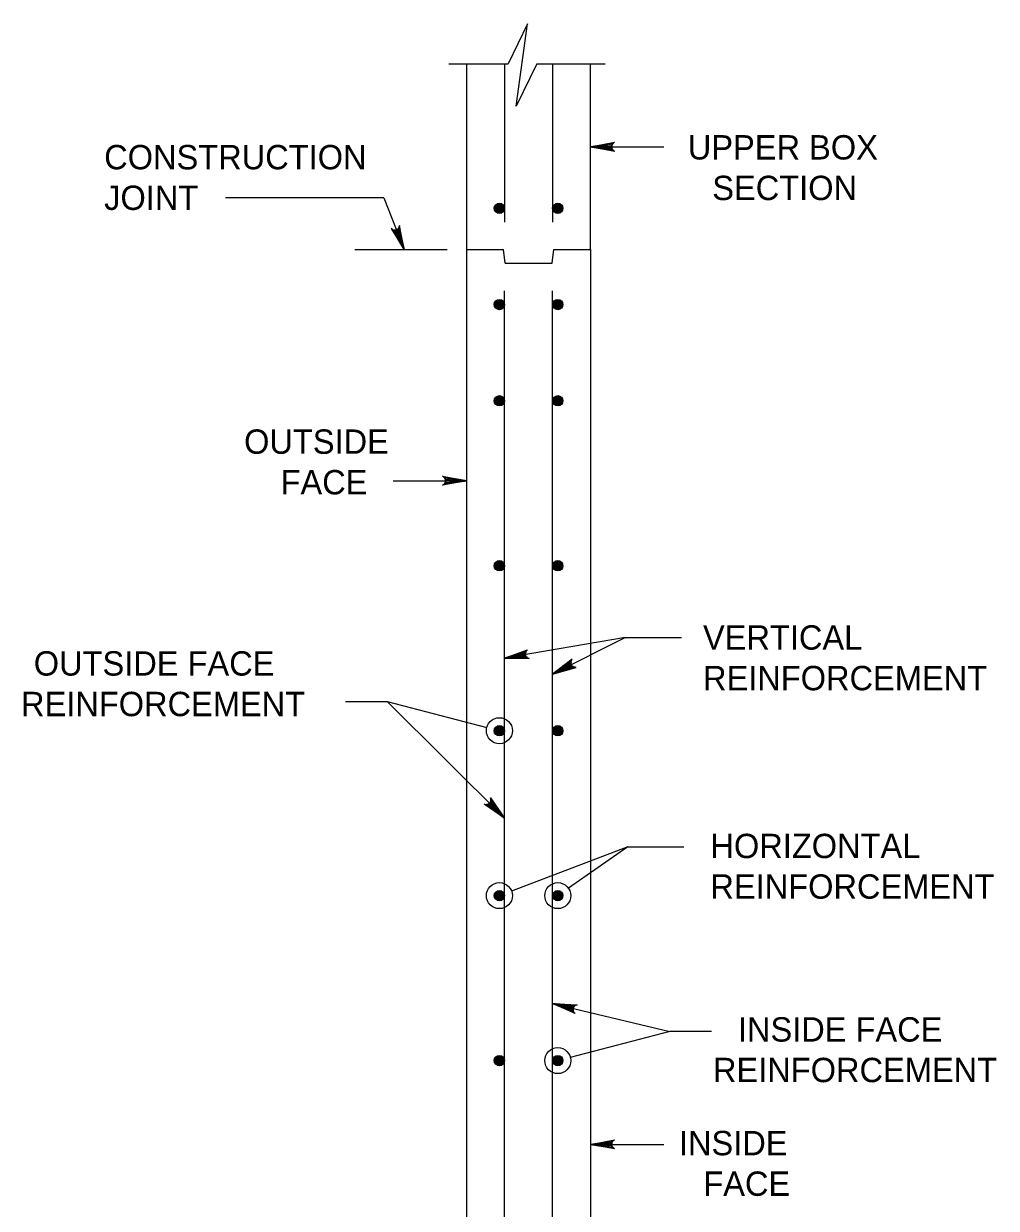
# Model space of a CAD drawing. Extents: x -6420 to 49575, y -4552 to 11624.
# Drawn here: x 2887 to 3280, y 6358.6 to 6837.4 of the extents above; entities that cross this region are included whole.
import ezdxf

# ---------------------------------------------------------------- set-up
doc = ezdxf.new("R2010")
doc.units = 0
doc.layers.add('1', color=7, linetype='Continuous')

msp = doc.modelspace()

# ---------------------------------------------------------------- linework, layer by layer
at = {"layer": '1'}
for p, q in [((3058.81, 6821.09), (3082.78, 6821.09)), ((3065.99, 6746.09), (3065.99, 6821.09)), ((3081.28, 6821.09), (3081.28, 6757.21)), ((3094.33, 6821.09), (3121.91, 6821.09)), ((3100.69, 6821.09), (3100.69, 6757.21)), ((3115.99, 6746.09), (3115.99, 6821.09)), ((3115.99, 6787.61), (3145.68, 6787.61)), ((3032.51, 6767.06), (2968.54, 6767.06)), ((3032.51, 6767.06), (3040.7, 6746.09)), ((3020.79, 6746.09), (3058.12, 6746.09)), ((3065.99, 6146.09), (3065.99, 6746.09)), ((3065.99, 6746.09), (3080.81, 6746.09)), ((3081.5, 6740.54), (3080.81, 6746.09)), ((3100.48, 6740.54), (3101.18, 6746.09)), ((3101.18, 6746.09), (3115.99, 6746.09)), ((3115.99, 6746.09), (3115.99, 6201.65)), ((3081.5, 6740.54), (3100.48, 6740.54)), ((3081.28, 6175.26), (3081.28, 6729.43)), ((3100.69, 6168.31), (3100.69, 6729.43)), ((3036.3, 6652.67), (3065.99, 6652.67)), ((3130.14, 6589.33), (3081.28, 6580.92)), ((3130.14, 6589.33), (3100.69, 6574.45)), ((3130.14, 6589.33), (3152.78, 6589.33)), ((3017.02, 6563.46), (3033.9, 6563.46)), ((3081.28, 6516.35), (3033.9, 6563.46)), ((3033.9, 6563.46), (3074.12, 6552.98)), ((3079.2, 6551.65), (3079.2, 6551.65)), ((3131.15, 6504.68), (3084.11, 6486.85)), ((3131.15, 6504.68), (3107.09, 6487.98)), ((3131.15, 6504.68), (3153.8, 6504.68)), ((3079.2, 6484.99), (3079.2, 6484.99)), ((3102.78, 6484.99), (3102.78, 6484.99)), ((3100.69, 6441.41), (3148.08, 6430.13)), ((3148.08, 6430.13), (3107.86, 6419.64)), ((3164.96, 6430.13), (3148.08, 6430.13)), ((3102.78, 6418.32), (3102.78, 6418.32)), ((3115.99, 6384.48), (3145.68, 6384.48))]:
    msp.add_line(p, q, dxfattribs=at)
for points in [[(3094.33, 6821.09), (3086, 6804.08), (3090.53, 6837.38), (3082.78, 6821.09)], [(3115.99, 6787.61), (3125.77, 6789.45), (3125.4, 6789.19), (3125.02, 6788.93), (3124.83, 6788.6), (3124.63, 6788.27), (3124.58, 6787.94), (3124.52, 6787.61), (3124.58, 6787.29), (3124.63, 6786.96), (3124.83, 6786.63), (3125.02, 6786.3), (3125.4, 6786.04), (3125.77, 6785.78), (3115.99, 6787.61), (3125.4, 6786.04), (3125.02, 6786.3), (3115.99, 6787.61), (3124.83, 6786.63), (3124.63, 6786.96), (3115.99, 6787.61), (3124.58, 6787.29), (3124.52, 6787.61), (3115.99, 6787.61), (3124.58, 6787.94), (3124.63, 6788.27), (3115.99, 6787.61), (3124.83, 6788.6), (3125.02, 6788.93), (3115.99, 6787.61), (3125.4, 6789.19)], [(3040.7, 6746.09), (3038.85, 6755.88), (3038.74, 6755.43), (3038.64, 6754.98), (3038.4, 6754.68), (3038.17, 6754.38), (3037.88, 6754.21), (3037.6, 6754.04), (3037.27, 6753.97), (3036.94, 6753.9), (3036.57, 6753.97), (3036.19, 6754.03), (3035.81, 6754.28), (3035.43, 6754.54), (3040.7, 6746.09), (3035.81, 6754.28), (3036.19, 6754.03), (3040.7, 6746.09), (3036.57, 6753.97), (3036.94, 6753.9), (3040.7, 6746.09), (3037.27, 6753.97), (3037.6, 6754.04), (3040.7, 6746.09), (3037.88, 6754.21), (3038.17, 6754.38), (3040.7, 6746.09), (3038.4, 6754.68), (3038.64, 6754.98), (3040.7, 6746.09), (3038.74, 6755.43)], [(3065.99, 6652.67), (3056.2, 6650.83), (3056.58, 6651.1), (3056.96, 6651.36), (3057.15, 6651.69), (3057.35, 6652.01), (3057.4, 6652.34), (3057.46, 6652.67), (3057.4, 6653), (3057.35, 6653.33), (3057.15, 6653.65), (3056.96, 6653.98), (3056.58, 6654.24), (3056.2, 6654.5), (3065.99, 6652.67), (3056.58, 6654.24), (3056.96, 6653.98), (3065.99, 6652.67), (3057.15, 6653.65), (3057.35, 6653.33), (3065.99, 6652.67), (3057.4, 6653), (3057.46, 6652.67), (3065.99, 6652.67), (3057.4, 6652.34), (3057.35, 6652.01), (3065.99, 6652.67), (3057.15, 6651.69), (3056.96, 6651.36), (3065.99, 6652.67), (3056.58, 6651.1)], [(3081.28, 6580.92), (3090.62, 6584.39), (3090.29, 6584.07), (3089.96, 6583.75), (3089.83, 6583.39), (3089.69, 6583.03), (3089.69, 6582.7), (3089.69, 6582.37), (3089.8, 6582.05), (3089.91, 6581.74), (3090.16, 6581.45), (3090.41, 6581.16), (3090.82, 6580.97), (3091.24, 6580.77), (3081.28, 6580.92), (3090.82, 6580.97), (3090.41, 6581.16), (3081.28, 6580.92), (3090.16, 6581.45), (3089.91, 6581.74), (3081.28, 6580.92), (3089.8, 6582.05), (3089.69, 6582.37), (3081.28, 6580.92), (3089.69, 6582.7), (3089.69, 6583.03), (3081.28, 6580.92), (3089.83, 6583.39), (3089.96, 6583.75), (3081.28, 6580.92), (3090.29, 6584.07)], [(3100.69, 6574.45), (3110.25, 6577.22), (3109.8, 6577.29), (3109.35, 6577.35), (3109.02, 6577.56), (3108.7, 6577.76), (3108.5, 6578.03), (3108.31, 6578.3), (3108.21, 6578.61), (3108.11, 6578.93), (3108.14, 6579.31), (3108.16, 6579.69), (3108.38, 6580.1), (3108.6, 6580.5), (3100.69, 6574.45), (3108.38, 6580.1), (3108.16, 6579.69), (3100.69, 6574.45), (3108.14, 6579.31), (3108.11, 6578.93), (3100.69, 6574.45), (3108.21, 6578.61), (3108.31, 6578.3), (3100.69, 6574.45), (3108.5, 6578.03), (3108.7, 6577.76), (3100.69, 6574.45), (3109.02, 6577.56), (3109.35, 6577.35), (3100.69, 6574.45), (3109.8, 6577.29)], [(3081.28, 6516.35), (3073.05, 6521.95), (3073.5, 6521.87), (3073.95, 6521.79), (3074.32, 6521.88), (3074.69, 6521.98), (3074.96, 6522.17), (3075.23, 6522.36), (3075.43, 6522.64), (3075.62, 6522.91), (3075.71, 6523.28), (3075.8, 6523.65), (3075.72, 6524.1), (3075.64, 6524.55), (3081.28, 6516.35), (3075.72, 6524.1), (3075.8, 6523.65), (3081.28, 6516.35), (3075.71, 6523.28), (3075.62, 6522.91), (3081.28, 6516.35), (3075.43, 6522.64), (3075.23, 6522.36), (3081.28, 6516.35), (3074.96, 6522.17), (3074.69, 6521.98), (3081.28, 6516.35), (3074.32, 6521.88), (3073.95, 6521.79), (3081.28, 6516.35), (3073.5, 6521.87)], [(3100.69, 6441.41), (3110.64, 6440.93), (3110.21, 6440.76), (3109.78, 6440.59), (3109.52, 6440.32), (3109.25, 6440.05), (3109.12, 6439.74), (3108.99, 6439.43), (3108.97, 6439.1), (3108.95, 6438.77), (3109.06, 6438.41), (3109.17, 6438.04), (3109.48, 6437.7), (3109.79, 6437.36), (3100.69, 6441.41), (3109.48, 6437.7), (3109.17, 6438.04), (3100.69, 6441.41), (3109.06, 6438.41), (3108.95, 6438.77), (3100.69, 6441.41), (3108.97, 6439.1), (3108.99, 6439.43), (3100.69, 6441.41), (3109.12, 6439.74), (3109.25, 6440.05), (3100.69, 6441.41), (3109.52, 6440.32), (3109.78, 6440.59), (3100.69, 6441.41), (3110.21, 6440.76)], [(3115.99, 6384.48), (3125.77, 6386.31), (3125.4, 6386.05), (3125.02, 6385.79), (3124.83, 6385.46), (3124.63, 6385.13), (3124.58, 6384.8), (3124.52, 6384.48), (3124.58, 6384.15), (3124.63, 6383.82), (3124.83, 6383.49), (3125.02, 6383.16), (3125.4, 6382.9), (3125.77, 6382.64), (3115.99, 6384.48), (3125.4, 6382.9), (3125.02, 6383.16), (3115.99, 6384.48), (3124.83, 6383.49), (3124.63, 6383.82), (3115.99, 6384.48), (3124.58, 6384.15), (3124.52, 6384.48), (3115.99, 6384.48), (3124.58, 6384.8), (3124.63, 6385.13), (3115.99, 6384.48), (3124.83, 6385.46), (3125.02, 6385.79), (3115.99, 6384.48), (3125.4, 6386.05)]]:
    msp.add_lwpolyline(points, dxfattribs=at)
for centre, radius in [((3079.2, 6762.76), 2.08), ((3079.2, 6762.76), 1.94), ((3102.78, 6762.76), 2.08), ((3102.78, 6762.76), 1.94), ((3079.2, 6762.76), 1.79), ((3079.2, 6762.76), 1.64), ((3079.2, 6762.76), 1.49), ((3079.2, 6762.76), 1.34), ((3079.2, 6762.76), 1.2), ((3079.2, 6762.76), 1.05), ((3079.2, 6762.76), 0.9), ((3079.2, 6762.76), 0.752), ((3079.2, 6762.76), 0.604), ((3079.2, 6762.76), 0.456), ((3079.2, 6762.76), 0.308), ((3079.2, 6762.76), 0.16), ((3102.78, 6762.76), 1.79), ((3102.78, 6762.76), 1.64), ((3102.78, 6762.76), 1.49), ((3102.78, 6762.76), 1.34), ((3102.78, 6762.76), 1.2), ((3102.78, 6762.76), 1.05), ((3102.78, 6762.76), 0.9), ((3102.78, 6762.76), 0.752), ((3102.78, 6762.76), 0.604), ((3102.78, 6762.76), 0.456), ((3102.78, 6762.76), 0.308), ((3102.78, 6762.76), 0.16), ((3079.2, 6723.87), 2.08), ((3079.2, 6723.87), 1.94), ((3079.2, 6723.87), 1.79), ((3079.2, 6723.87), 1.64), ((3079.2, 6723.87), 1.49), ((3079.2, 6723.87), 1.34), ((3079.2, 6723.87), 1.2), ((3079.2, 6723.87), 1.05), ((3079.2, 6723.87), 0.9), ((3079.2, 6723.87), 0.752), ((3079.2, 6723.87), 0.604), ((3079.2, 6723.87), 0.456), ((3079.2, 6723.87), 0.308), ((3079.2, 6723.87), 0.16), ((3102.78, 6723.87), 2.08), ((3102.78, 6723.87), 1.94), ((3102.78, 6723.87), 1.79), ((3102.78, 6723.87), 1.64), ((3102.78, 6723.87), 1.49), ((3102.78, 6723.87), 1.34), ((3102.78, 6723.87), 1.2), ((3102.78, 6723.87), 1.05), ((3102.78, 6723.87), 0.9), ((3102.78, 6723.87), 0.752), ((3102.78, 6723.87), 0.604), ((3102.78, 6723.87), 0.456), ((3102.78, 6723.87), 0.308), ((3102.78, 6723.87), 0.16), ((3079.2, 6684.99), 2.08), ((3079.2, 6684.99), 1.94), ((3079.2, 6684.99), 1.79), ((3079.2, 6684.99), 1.64), ((3079.2, 6684.99), 1.49), ((3079.2, 6684.99), 1.34), ((3079.2, 6684.99), 1.2), ((3079.2, 6684.99), 1.05), ((3079.2, 6684.99), 0.9), ((3079.2, 6684.99), 0.752), ((3079.2, 6684.99), 0.604), ((3079.2, 6684.99), 0.456), ((3079.2, 6684.99), 0.308), ((3079.2, 6684.99), 0.16), ((3102.78, 6684.99), 2.08), ((3102.78, 6684.99), 1.94), ((3102.78, 6684.99), 1.79), ((3102.78, 6684.99), 1.64), ((3102.78, 6684.99), 1.49), ((3102.78, 6684.99), 1.34), ((3102.78, 6684.99), 1.2), ((3102.78, 6684.99), 1.05), ((3102.78, 6684.99), 0.9), ((3102.78, 6684.99), 0.752), ((3102.78, 6684.99), 0.604), ((3102.78, 6684.99), 0.456), ((3102.78, 6684.99), 0.308), ((3102.78, 6684.99), 0.16), ((3079.2, 6618.32), 2.08), ((3079.2, 6618.32), 1.94), ((3079.2, 6618.32), 1.79), ((3079.2, 6618.32), 1.64), ((3079.2, 6618.32), 1.49), ((3079.2, 6618.32), 1.34), ((3079.2, 6618.32), 1.2), ((3079.2, 6618.32), 1.05), ((3079.2, 6618.32), 0.9), ((3079.2, 6618.32), 0.752), ((3079.2, 6618.32), 0.604), ((3079.2, 6618.32), 0.456), ((3079.2, 6618.32), 0.308), ((3079.2, 6618.32), 0.16), ((3102.78, 6618.32), 2.08), ((3102.78, 6618.32), 1.94), ((3102.78, 6618.32), 1.79), ((3102.78, 6618.32), 1.64), ((3102.78, 6618.32), 1.49), ((3102.78, 6618.32), 1.34), ((3102.78, 6618.32), 1.2), ((3102.78, 6618.32), 1.05), ((3102.78, 6618.32), 0.9), ((3102.78, 6618.32), 0.752), ((3102.78, 6618.32), 0.604), ((3102.78, 6618.32), 0.456), ((3102.78, 6618.32), 0.308), ((3102.78, 6618.32), 0.16), ((3079.2, 6551.65), 5.25), ((3079.2, 6551.65), 2.08), ((3079.2, 6551.65), 1.94), ((3079.2, 6551.65), 1.79), ((3079.2, 6551.65), 1.64), ((3079.2, 6551.65), 1.49), ((3079.2, 6551.65), 1.34), ((3079.2, 6551.65), 1.2), ((3079.2, 6551.65), 1.05), ((3079.2, 6551.65), 0.9), ((3079.2, 6551.65), 0.752), ((3079.2, 6551.65), 0.604), ((3079.2, 6551.65), 0.456), ((3079.2, 6551.65), 0.308), ((3079.2, 6551.65), 0.16), ((3102.78, 6551.65), 2.08), ((3102.78, 6551.65), 1.94), ((3102.78, 6551.65), 1.79), ((3102.78, 6551.65), 1.64), ((3102.78, 6551.65), 1.49), ((3102.78, 6551.65), 1.34), ((3102.78, 6551.65), 1.2), ((3102.78, 6551.65), 1.05), ((3102.78, 6551.65), 0.9), ((3102.78, 6551.65), 0.752), ((3102.78, 6551.65), 0.604), ((3102.78, 6551.65), 0.456), ((3102.78, 6551.65), 0.308), ((3102.78, 6551.65), 0.16), ((3079.2, 6484.99), 5.25), ((3079.2, 6484.99), 2.08), ((3102.78, 6484.99), 5.25), ((3102.78, 6484.99), 2.08), ((3079.2, 6484.99), 1.94), ((3079.2, 6484.99), 1.79), ((3079.2, 6484.99), 1.64), ((3079.2, 6484.99), 1.49), ((3079.2, 6484.99), 1.34), ((3079.2, 6484.99), 1.2), ((3079.2, 6484.99), 1.05), ((3079.2, 6484.99), 0.9), ((3079.2, 6484.99), 0.752), ((3079.2, 6484.99), 0.604), ((3079.2, 6484.99), 0.456), ((3079.2, 6484.99), 0.308), ((3079.2, 6484.99), 0.16), ((3102.78, 6484.99), 1.94), ((3102.78, 6484.99), 1.79), ((3102.78, 6484.99), 1.64), ((3102.78, 6484.99), 1.49), ((3102.78, 6484.99), 1.34), ((3102.78, 6484.99), 1.2), ((3102.78, 6484.99), 1.05), ((3102.78, 6484.99), 0.9), ((3102.78, 6484.99), 0.752), ((3102.78, 6484.99), 0.604), ((3102.78, 6484.99), 0.456), ((3102.78, 6484.99), 0.308), ((3102.78, 6484.99), 0.16), ((3079.2, 6418.32), 2.08), ((3079.2, 6418.32), 1.94), ((3079.2, 6418.32), 1.79), ((3102.78, 6418.32), 5.25), ((3102.78, 6418.32), 2.08), ((3102.78, 6418.32), 1.94), ((3102.78, 6418.32), 1.79), ((3079.2, 6418.32), 1.64), ((3079.2, 6418.32), 1.49), ((3079.2, 6418.32), 1.34), ((3079.2, 6418.32), 1.2), ((3079.2, 6418.32), 1.05), ((3079.2, 6418.32), 0.9), ((3079.2, 6418.32), 0.752), ((3079.2, 6418.32), 0.604), ((3079.2, 6418.32), 0.456), ((3079.2, 6418.32), 0.308), ((3079.2, 6418.32), 0.16), ((3102.78, 6418.32), 1.64), ((3102.78, 6418.32), 1.49), ((3102.78, 6418.32), 1.34), ((3102.78, 6418.32), 1.2), ((3102.78, 6418.32), 1.05), ((3102.78, 6418.32), 0.9), ((3102.78, 6418.32), 0.752), ((3102.78, 6418.32), 0.604), ((3102.78, 6418.32), 0.456), ((3102.78, 6418.32), 0.308), ((3102.78, 6418.32), 0.16)]:
    msp.add_circle(centre, radius, dxfattribs=at)

# ---------------------------------------------------------------- texts
for s, height, p in [('UPPER BOX', 9.843, (3155.35, 6782.49)), ('CONSTRUCTION', 9.8425, (2919.49, 6778.52)), ('SECTION', 9.843, (3165.23, 6766.09)), ('JOINT', 9.843, (2919.49, 6762.11)), ('OUTSIDE', 9.843, (2976.03, 6663.56)), ('FACE', 9.843, (2990.79, 6647.16)), ('VERTICAL', 9.843, (3161.48, 6584.4)), ('OUTSIDE FACE', 9.8425, (2891.04, 6573.92)), ('REINFORCEMENT', 9.8425, (3161.48, 6567.99)), ('REINFORCEMENT', 9.8425, (2885.89, 6557.52)), ('HORIZONTAL', 9.843, (3164.48, 6500.15)), ('REINFORCEMENT', 9.8425, (3164.48, 6483.75)), ('INSIDE FACE', 9.8425, (3175.59, 6426.01)), ('REINFORCEMENT', 9.8425, (3165.51, 6409.61)), ('INSIDE', 9.843, (3151.76, 6380.07)), ('FACE', 9.843, (3161.61, 6363.67))]:
    msp.add_text(s, height=height, dxfattribs=at).set_placement(p)

doc.saveas('drawing.dxf')
